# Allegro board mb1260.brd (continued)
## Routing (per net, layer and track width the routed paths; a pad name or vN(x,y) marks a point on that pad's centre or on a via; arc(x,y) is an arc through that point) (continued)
STMOD+_UART4_TXD: length 79.6
  TOP w0.127: U8.E12 v2(38.74,48.76)
  BOTTOM w0.127: P1.17 74.91,74.5 76.26,73.15 76.26,56.45 65.66,45.85 65.66,36.58 65.28,36.2 63.12,36.2 62.74,36.58 62.74,39.75 61.85,40.64 60.96,40.64 59.31,42.29 57.91,42.29 57.84,42.37 57.8,42.37 50.39,49.78 42.26,49.78 41.63,49.15 41.29,49.15 41.17,49.26 40.5,49.26 40,48.76 v2(38.74,48.76)
SYS_B_USER: length 76.7
  TOP w0.127: U8.N3 v2(32.24,42.91)
  L4_SIG w0.102: v1(35.81,23.11) 35.31,23.62 35.31,24.64 35.81,25.15 35.81,34.39 34.44,35.76 34.44,40.26 33.32,41.38 33.32,43.12 33.19,43.26 32.6,43.26 v2(32.24,42.91)
  BOTTOM w0.127: v1(35.81,23.11) 36.45,23.11 37.33,22.24 55.96,22.24 56.22,21.97 60.8,21.97 63.47,24.64 64.52,24.64 69.9,30.02 69.9,38.02 71.88,40.01 71.88,42.75 72.14,43 SB33.1
SYS_LD_USER1: length 50.5
  TOP w0.127: v1(10.67,50.67) 11.05,50.29 13.66,50.29 21.62,42.33 21.62,34.2 23.18,32.64 34.29,32.64 34.75,33.1 34.75,35.85 33.95,36.65 33.95,38.14 32.56,39.52 U8.R3
  BOTTOM w0.127: v1(10.67,50.67) 9.65,51.69 R47.1
SYS_LD_USER2: length 50.9
  TOP w0.127: U8.R4 32.97,41.69 32.97,39.73 34.33,38.37 34.33,36.81 35.13,36.01 35.13,32.84 34.54,32.26 22.99,32.26 21.21,34.04 21.21,42.16 13.46,49.91 10.79,49.91 v1(10.67,49.78)
  BOTTOM w0.127: R48.1 10.29,49.4 v1(10.67,49.78)
SYS_STLINK_JTCK: length 17.3
  TOP w0.127: v1(48.45,58.15) 48.51,58.09 48.51,57.38 48.53,57.36 48.53,57 SB12.2 49.69,56.87 R38.2 ; U8.A14 39.71,51.27 40.22,51.78 v2(40.22,51.98)
  BOTTOM w0.127: v1(48.45,58.15) 48.51,58.09 48.51,54.36 47.88,53.72 43.31,53.72 41.8,52.21 40.87,52.21 40.64,51.98 v2(40.22,51.98)
SYS_STLINK_JTDO-SWO: length 17.1
  TOP w0.127: U8.A10 37.11,51.97 37.31,52.17 37.31,52.79 37.57,53.05 37.57,53.27 v2(37.6,53.3) ; v1(46.86,55.91) 48.49,55.91 48.62,55.78 48.62,54.88 SB13.2 48.69,54.86 R40.2
  BOTTOM w0.127: v1(46.86,55.91) 45.97,55.91 44.65,54.58 38.94,54.58 37.66,53.3 v2(37.6,53.3)
SYS_STLINK_JTMS: length 16.9
  TOP w0.127: v2(41.27,51.82) 41.15,51.82 U8.A15 ; v1(49.07,58.29) 48.66,58.7 SB11.2 48.69,59.44 R32.2
  BOTTOM w0.127: v2(41.27,51.82) 42.04,51.82 42.8,52.58 44.69,52.58 45.33,53.21 48.01,53.21 49.07,54.28 v1(49.07,58.29)
T_JTCK: length 29.7
  TOP w0.127: U2.26 44.56,74.59 43.84,73.87 U2.15 43.84,71.85 44.96,70.74 48.9,70.74 49.66,69.98 49.66,65.82 46.74,62.9 46.74,58.6 47.68,57.66 SB12.1
T_JTMS: length 19.2
  TOP w0.127: v1(52.07,73.15) 52.07,74.42 R23.1 51.41,75.08 U2.27 ; SB11.1 47.68,59.61 48.01,59.94 v1(48.01,60.83)
  L4_SIG w0.102: v1(48.01,60.83) 48.01,64.77 50.8,67.56 50.8,70.87 52.07,72.14 v1(52.07,73.15)
T_NRST: length 15.2
  TOP w0.127: SB10.1 47.81,62.48 47.81,62.49 47.88,62.56 47.88,63.5 50.04,65.66 50.04,70.48 49.28,71.25 45.6,71.25 45.34,71.5 U2.18
T_SWDIO_IN: length 1.5
  TOP w0.127: 51.44,74.04 51.39,74.08 U2.25
T_SWO: length 29.4
  TOP w0.127: SB13.1 46.86,54.86 45.47,56.25 45.47,62.36 48.9,65.79 v1(48.9,66.8) ; v1(46.61,76.45) 47.24,77.08 U2.31
  BOTTOM w0.127: v1(48.9,66.8) 49.4,67.31 49.4,73.66 v1(46.61,76.45)
TAG_NRST: length 8.2
  TOP w0.127: R28.1 53.47,62.36 54.1,62.99 56.52,62.99 57.15,62.36 57.15,60.83 CN9.10
TAG_SWCLK: length 3.7
  TOP w0.127: 55.37,56.52 52.58,56.52 52.45,56.39 R38.1
TAG_SWDIO: length 3.8
  TOP w0.127: CN9.2 52.07,59.05 R32.1
TAG_SWO: length 12
  TOP w0.127: R40.1 51.69,53.21 52.32,52.58 57.66,52.58 58.17,53.09 58.17,54.74 57.66,55.24 CN9.6
USB_OTGFS_CN_N: length 3.3
  BOTTOM w0.155: CN18.2 51.95,4.99 52.08,5.12 52.08,5.8 51.25,6.64 U22.6
USB_OTGFS_CN_P: length 3.3
  BOTTOM w0.155: U22.4 53.15,6.61 52.47,5.93 52.47,5.12 52.6,4.99 CN18.3
USB_OTGFS_ID: length 57.3
  TOP w0.127: v2(42.64,48.87) 42.36,49.15 41.4,49.15 41.15,49.4 40.68,49.4 U8.D15
  L4_SIG w0.102: v2(42.64,48.87) 42.77,48.74 46.96,48.74 48.77,46.94 48.77,46.15 54.74,40.18 54.74,38.48 55.88,37.34 55.88,27.64 56.26,27.26 56.26,23.65 56.92,22.99 56.92,12.37 v1(55.6,11.05)
  BOTTOM w0.127: CN18.4 53.25,5.47 54.71,6.93 U23.1 54.71,9.37 55.6,10.26 v1(55.6,11.05)
USB_OTGFS_N: length 55.4
  TOP w0.155: v1(51.83,11.27) 52,11.44 52,12.79 55.02,15.8 55.02,46.98 51.84,50.16 41.18,50.16 40.88,49.87 40.5,49.87 U8.C15
  BOTTOM w0.155: U22.1 51.25,9.92 52,10.67 52,11.11 v1(51.83,11.27)
USB_OTGFS_OVCR: length 64.1
  TOP w0.127: U8.R12 38.31,41.83 38.31,41.05 38.43,40.92 38.43,40.32 v2(39.59,39.16) ; U14.3 61.54,9.47 R79.1 v1(61.59,8.13) 61.59,7.75 60.96,7.11 v1(60.96,5.08)
  L4_SIG w0.102: v2(39.59,39.16) 39.64,39.16 39.98,38.82 39.98,18.58 40.44,18.12 40.44,14.91 v1(38.99,13.46)
  BOTTOM w0.127: LD10.2 v1(60.96,5.08) ; v1(38.99,13.46) 38.99,12.95 39.88,12.07 40.77,12.07 42.04,10.8 46.05,10.8 46.3,11.05 50.67,11.05 51.69,12.07 58.22,12.07 61.59,8.69 v1(61.59,8.13)
USB_OTGFS_P: length 56
  TOP w0.155: U8.B15 40.5,50.25 40.72,50.25 41.02,50.55 51.99,50.55 55.4,47.14 55.4,15.65 52.38,12.63 52.38,11.44 v1(52.54,11.27)
  BOTTOM w0.155: U22.3 53.15,9.92 52.38,10.69 52.38,11.11 v1(52.54,11.27)
USB_OTGFS_PPWR_EN: length 46
  TOP w0.127: v2(41.53,46.48) 41.4,46.48 41.12,46.76 40.67,46.76 40.62,46.81 40.04,46.81 U8.H14 ; R72.1 59.94,17.91 57.71,20.14 57.71,22.68 56.52,23.88 v1(56.52,32.51)
  BOTTOM w0.127: v1(56.52,32.51) 55.5,33.53 55.5,40.31 52.32,43.48 45.92,43.48 45.78,43.62 45.28,43.62 44.83,44.07 44.83,44.96 44.07,45.72 42.27,45.72 41.66,46.33 41.66,46.35 v2(41.53,46.48)
USB_OTGFS_VBUS: length 73.5
  TOP w0.254: v2(41.91,48.39) 41.87,48.43 U8.E15
  TOP w0.508: U14.1 58.11,7.94 C77.1 56.62,9.3 55.22,9.3 54.47,10.05 v4(54.47,11.2) ; v4(50.01,10.41) 50.01,11.07 49.15,11.94 48.13,11.94 47.24,12.83 R77.2
  L4_SIG w0.508: v2(41.91,48.39) 41.91,47.75 42.29,47.37 46.41,47.37 47.19,46.58 47.19,45.73 48.14,44.78 49.23,44.78 54.18,39.83 54.18,38.28 55.37,37.08 55.37,27.43 55.75,27.05 55.75,12.27 54.69,11.2 v4(54.47,11.2) 53.85,11.2 52.78,12.27 51.31,12.27 50.01,10.97 v4(50.01,10.41)
  BOTTOM w0.254: CN18.1 51.3,5.34 50.61,6.03 50.22,6.03 U24.1
  BOTTOM w0.508: U24.1 49.67,7.13 R99.1 50.01,8.85 v4(50.01,10.41)
USB_OTGHS_CN_N: length 2.8
  TOP w0.155: U15.2 28.05,6.18 28.11,6.12 28.11,5.87 v1(27.92,5.68)
  BOTTOM w0.155: v1(27.92,5.68) 28.08,5.52 28.08,5.12 27.95,4.99 CN19.2
USB_OTGHS_CN_P: length 2.8
  TOP w0.155: U15.3 28.55,6.18 28.49,6.12 28.49,5.83 v1(28.63,5.68)
  BOTTOM w0.155: v1(28.63,5.68) 28.47,5.52 28.47,5.12 28.6,4.99 CN19.3
USB_OTGHS_ID: length 44.7
  TOP w0.127: U8.P12 38.08,42.25 38.08,41.27 38.05,41.24 38.05,40.14 39.29,38.9 39.29,38.77 v2(39.47,38.58) ; v1(29.59,5.72) 29.05,6.26 U15.4 29.16,6.86 29.72,6.86 32.13,9.27 32.13,10.8 39.24,17.91 v1(39.75,17.91)
  L4_SIG w0.102: v2(39.47,38.58) 39.62,38.43 39.62,18.03 v1(39.75,17.91)
  BOTTOM w0.127: CN19.4 29.25,5.37 v1(29.59,5.72)
USB_OTGHS_N: length 39.6
  TOP w0.155: U15.7 28.05,8.3 28.11,8.36 28.11,9.21 37.74,18.85 37.74,31.68 40.39,34.32 40.39,40.69 39.85,41.22 39.85,41.8 U8.R14
USB_OTGHS_OVCR: length 54.5
  TOP w0.127: v1(39.62,13.21) R78.2 ; U8.L13 v2(39.39,44.21)
  L4_SIG w0.102: v1(39.62,13.21) 40.56,12.27 45.67,12.27 48.64,15.24 49.78,15.24 51.18,16.64 51.94,16.64 53.52,18.21 53.52,18.63 53.52,32.46 52.96,33.02 52.96,37.16 48.34,41.78 45.97,41.78 45.72,42.04 42.82,42.04 42.1,42.75 41.29,42.75 41.14,42.61 40.85,42.61 40.7,42.75 40.59,42.75 40.04,43.31 39.88,43.31 39.75,43.43 39.75,43.84 v2(39.39,44.21)
USB_OTGHS_P: length 39.6
  TOP w0.155: U15.6 28.55,8.3 28.49,8.36 28.49,9.06 38.13,18.69 38.13,31.52 40.77,34.16 40.77,40.84 40.23,41.38 40.23,41.8 U8.R15
USB_OTGHS_PPWR_EN: length 60.7
  TOP w0.127: U8.K12 v2(38.74,44.86) ; v1(38.73,12.45) 38.73,12.9 38.3,13.34 37.97,13.34 37.97,11.93 U13.4
  L4_SIG w0.102: v2(38.74,44.86) 39.55,44.86 40.01,44.4 41.33,44.4 42.05,43.68 45.86,43.68 46.99,42.55 48.59,42.55 53.72,37.41 53.72,33.4 54.36,32.77 54.36,26.97 54.91,26.42 54.91,17.65 54.58,17.32 53.52,17.32 52.22,16.03 51.46,16.03 49.91,14.48 48.9,14.48 46.02,11.61 39.57,11.61 v1(38.73,12.45)
USB_OTGHS_VBUS: length 39.1
  TOP w0.127: 38.99,40.64 38.75,40.88 38.75,42.26 U8.P13
  TOP w0.381: 38.99,40.64 39.38,40.25 v2(39.38,39.98)
  L4_SIG w0.508: v2(39.38,39.98) 38.89,39.49 38.89,38.89 37.91,37.91 37.91,34.94 37.47,34.49 37.47,28.3 38.53,27.23 38.53,21.62 33.1,16.18 v1(31.7,16.18)
  BOTTOM w0.508: R98.1 31.37,9.91 31.7,10.24 v1(31.7,16.18)
USB_RENUMN: length 2.3
  TOP w0.127: U2.38 47.84,81.88 48.13,82.17 48.26,82.17 R7.2
USB_STLK_CN_N: length 3.4
  TOP w0.155: U21.1 53.78,90.62 52.98,91.42 52.98,91.89 53.11,92.02 CN1.2
USB_STLK_CN_P: length 3.4
  TOP w0.155: U21.3 51.88,90.62 52.59,91.33 52.59,91.89 52.46,92.02 CN1.3
USB_STLK_ID: length 3.1
  TOP w0.127: CN1.4 51.81,91.96 R9.2
USB_STLK_N: length 13.9
  TOP w0.155: U21.6 53.78,85.66 53.09,84.96 53.09,84.51 53.98,83.62 53.98,78.74 52.88,77.64 50.77,77.64 50.72,77.59 U2.32
USB_STLK_P: length 13.3
  TOP w0.155: U2.33 50.69,78.08 50.75,78.03 52.72,78.03 53.59,78.9 53.59,83.46 52.7,84.35 52.7,84.9 R10.2 U21.4
VCAP1: length 12.2
  TOP w0.254: U8.M10 v2(37.44,43.56)
  TOP w0.508: v1(44.4,37.72) 44.4,38.04 43.74,38.7 C58.2
  L4_SIG w0.381: v2(37.44,43.56) 37.72,43.56 38.25,43.03 38.25,42.7 38.89,42.05 38.89,42.05 39.2,41.74 40.6,41.74 41.19,41.16 41.62,41.16 42.3,40.48 42.3,40.45
  L4_SIG w0.457: v1(44.4,37.72) 44.4,38.35 42.3,40.45
VCAP2: length 5.3
  TOP w0.254: v2(39.39,47.46) 39.07,47.78 U8.F13
  TOP w0.508: v1(42.67,48.26) 43.36,48.26 C49.2
  BOTTOM w0.508: v2(39.39,47.46) 39.71,47.46 40.01,47.75 42.16,47.75 v1(42.67,48.26)
VCP_RX: length 35.4
  TOP w0.127: SB8.1 41.97,68.33 47.12,68.33 CN6.2 ; v2(40.82,47.13) U8.G15
  L4_SIG w0.102: v2(40.82,47.13) 40.82,48 42.48,49.66 45.47,49.66 46.35,50.55 46.35,57.91 47.57,59.13 47.57,66.62 48.26,67.31 CN6.2
VCP_TX: length 32.5
  TOP w0.127: CN6.1 45.26,69.01 SB9.1 ; U8.H15 40.81,46.48 v2(40.9,46.39)
  L4_SIG w0.102: CN6.1 46.48,68.71 46.48,67.06 47.24,66.29 47.24,59.44 46.05,58.24 46.05,50.8 45.34,50.09 41.25,50.09 41.08,49.92 41.08,49.51 40.47,48.9 40.47,46.83 v2(40.9,46.39)
VL: length 12.3
  TOP w0.508: 25.64,24.51 C72.2 26.29,23.9 ; 23.65,25.27 L4.2 ; L4.2 24.26,24.62 ; L4.2 24.87,25.27 ; L6.1 26.8,21.18 ; L6.1 25.32,20.4 ; L6.1 28.27,20.4 ; 24.27,20.4 U12.1 23.86,21 ; C73.2 25.48,22.61 ; C73.2 24.69,23.57 ; C73.2 23.9,22.61 ; C73.2 24.69,21.64 ; 25.96,25.78 C70.2 26.44,26.26
VREF+: length 134.1
  TOP w0.254: U8.P1 31.15,42.58 31.05,42.48 30.92,42.48 29.51,41.07 29.51,39.85 28.27,38.61 C59.2
  TOP w0.508: C59.2 28.19,37.34 C64.1 28.31,36.21 R62.1 27.9,34.01 v1(23.6,34.01) ; C50.2 R53.2 62.48,45.85 62.74,46.1 64.64,46.1 65.53,45.21 v1(65.53,6.99)
  L4_SIG w0.508: v1(26.24,7.59) 26.24,8.59 27.08,9.42 45.06,9.42 46.95,7.53 46.96,7.54 47.53,7.54 47.58,7.49 61.85,7.49 62.87,6.48 65.02,6.48 v1(65.53,6.99)
  BOTTOM w0.508: v1(26.24,7.59) 23.39,7.59 19.24,11.75 19.24,29.65 v1(23.6,34.01)
WIFI_CH_PD: length 67
  TOP w0.127: U8.D11 37.75,49.08 37.44,48.77 v2(37.44,48.74)
  BOTTOM w0.127: CN14.6 7.34,24.66 7.34,26.09 R95.2 12.49,31.24 12.49,47.17 14.78,49.45 14.78,53.55 16.61,55.37 17.18,55.37 17.81,55.37 20.73,58.29 30.4,58.29 31.3,57.39 31.67,57.39 31.96,57.1 33.36,57.1 34.05,56.41 34.05,55.55 34.54,55.05 34.54,52.45 34.97,52.02 35.56,52.02 35.76,51.82 35.76,51.33 36.35,50.75 37.62,50.75 37.82,50.55 37.82,49.15 37.44,48.76 v2(37.44,48.74)
WIFI_GPIO_0: length 71.1
  TOP w0.127: U8.A8 35.76,51.08 35.76,51.99 36.22,52.45 36.22,52.78 36.65,53.21 v2(36.65,53.47)
  BOTTOM w0.127: CN14.3 7.37,21.79 5.38,21.79 4.65,22.53 4.65,25.93 R93.2 11.66,32.94 11.66,47.6 13.39,49.33 13.39,53.23 16.29,56.13 17.49,56.13 20.41,59.05 30.71,59.05 31.07,58.7 33.03,58.7 34.32,57.4 35.15,57.4 36.65,55.91 v2(36.65,53.47)
WIFI_GPIO_2: length 72.5
  TOP w0.127: v1(37.97,55.63) 38.4,55.19 38.4,52.81 38.18,52.58 38.18,51.41 38.1,51.33 38.1,50.71 U8.B11
  BOTTOM w0.127: v1(37.97,55.63) 37.54,56.06 37.16,56.06 35.38,57.84 34.43,57.84 33.18,59.08 31.22,59.08 30.87,59.44 20.25,59.44 17.33,56.52 16.13,56.52 13,53.39 13,49.64 11.25,47.89 11.25,33.93 R96.2 3.33,26.01 3.33,24.64 4.27,23.7 4.27,22.35 CN14.5
WIFI_RST: length 59.6
  TOP w0.127: U8.A7 35.04,51.15 v2(35.04,51.56)
  BOTTOM w0.127: v2(35.04,51.56) 34.62,51.56 34.14,52.04 34.14,53.77 32.93,54.98 32.93,56.17 32.42,56.68 31.84,56.68 31.51,57.01 31.14,57.01 30.24,57.91 20.89,57.91 17.92,54.94 16.76,54.94 15.16,53.34 15.16,49.07 12.88,46.78 12.88,30.35 R94.2 8.56,26.04 8.56,23.34 CN14.4
WIFI_RX: length 63.9
  TOP w0.102: 38.74,52.07 38.41,51.74 U8.A12
  TOP w0.127: 38.74,52.07 38.74,52.58 v2(38.86,52.7)
  BOTTOM w0.127: v2(38.86,52.7) 37.08,52.7 36.86,52.48 36.17,52.48 35.99,52.3 35.23,52.3 34.95,52.58 34.95,53.64 35.13,53.82 35.13,56.44 34.54,57.02 33.98,57.02 33.44,57.56 32.03,57.56 31.83,57.77 31.45,57.77 30.55,58.67 20.57,58.67 17.65,55.75 16.45,55.75 13.77,53.07 13.77,49.07 12.11,47.42 12.11,32.38 6.68,26.95 R92.1
WIFI_TX: length 60.5
  TOP w0.102: v2(36.8,48.13) 37.06,48.39 37.72,48.39 U8.D12
  BOTTOM w0.102: v2(36.8,48.13) 36.8,48.14 36.2,48.74 35.36,48.74 34.24,49.87 34.24,50.5 33.29,51.44 33.29,51.82
  BOTTOM w0.127: R97.2 13.26,29.46 13.26,46.53 15.54,48.82 15.54,53.14 16.97,54.56 18.07,54.56 18.44,54.93 19.36,54.93 20.1,55.67 20.1,56.32 21.31,57.53 30.08,57.53 30.98,56.63 31.35,56.63 31.68,56.3 32.26,56.3 32.55,56.01 32.55,54.6 33.29,53.85 33.29,51.82

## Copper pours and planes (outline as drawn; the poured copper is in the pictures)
1V8 on TOP: 1.84,44.51 1.52,44.83 1.52,48.13 1.78,48.39 4.45,48.39 4.57,48.51 4.57,50.04 4.83,50.29 9.02,50.29 9.4,49.91 9.4,45.59 7.75,43.94 7.75,43.31 6.73,43.31 6.73,43.94 6.16,44.51
1V8 on L4_SIG: 17.65,64.39 17.91,64.14 17.91,61.34 17.53,60.96 10.92,60.96 9.78,59.82 9.78,49.66 5.59,45.47 5.59,41.66 5.21,41.27 1.91,41.27 1.52,41.66 1.52,46.41 6.48,51.36 6.48,62.48 8.38,64.39
3V3 on TOP (solid shape): 5.72,65.02 6.05,65.35 6.32,65.08 5.78,64.54 5.71,64.61 5.64,64.54 5.1,65.08 5.38,65.36
3V3 on BOTTOM (solid shape): 25.34,74.33 25.4,74.39 25.67,74.12 25.13,73.58 25.09,73.62 25.05,73.58 24.51,74.12 24.78,74.39 24.84,74.33 25.09,74.58
3V3 on TOP: 9.14,43.43 11.43,43.43 11.68,43.18 11.68,40.01 11.3,39.62 9.02,39.62 8.64,40.01 8.64,42.93
3V3 on TOP: 58.67,65.66 62.23,65.66 62.61,66.04 62.61,67.31 62.48,67.44 61.85,67.44 61.59,67.69 58.8,67.69 58.55,67.44 54.1,67.44 53.72,67.06 53.72,65.02 54.1,64.64 57.66,64.64
3V3 on L3_VCC: outline of 97 points within 0.51,0.51 80.49,96.49
3V3_ST_LINK on TOP: 57.02,73.66 62.23,73.66 62.48,73.41 62.48,72.01 62.23,71.75 60.83,71.75 60.38,72.21 56.95,72.21 56.77,72.39 56.77,73.41
3V3_ST_LINK on L3_VCC: 38.97,72.14 37.82,73.28 33.25,73.28 32.77,73.77 32.77,96.49 78.49,96.49 79.91,95.9 80.49,94.49 80.49,74.17 70.51,74.17 68.47,72.14
5V on TOP: 64.14,67.18 64.39,67.44 64.39,69.22 64.14,69.47 64.14,70.74 64.26,70.87 65.15,70.87 65.79,70.23 66.17,70.23 66.29,70.1 66.29,69.09 66.42,68.96 66.42,67.69 66.04,67.31 66.04,66.17 65.91,66.04 64.39,66.04 64.14,66.29
5V on TOP: 80.44,45.91 80.44,33.33 79.76,32.64 79.65,32.64 79.29,32.28 75.93,32.28 75.83,32.38 75.83,32.86 76.09,33.12 76.09,34.46 76.08,34.46 75.83,34.71 75.83,35.25 76.1,35.52 76.1,36.94 76.09,36.94 75.83,37.2 75.83,37.86 76.1,38.13 76.1,39.49 76.07,39.49 75.83,39.72 75.83,40.39 76.15,40.71 76.15,42.01 76.15,42.01 75.83,42.33 75.83,42.95 76.18,43.29 76.18,44.05 76.17,44.06 76.17,44.24 74.95,45.46 74.95,66.51 74.01,67.44 71.12,67.44 70.66,67.9 70.66,73.21 71.11,73.66 74.71,73.66 75.14,73.22 77.38,73.22 80.26,70.34
5V on L3_VCC: 55.86,12.57 55.37,13.06 55.37,18.52 53.95,19.94 40.66,19.94 39.37,18.65 39.37,13.69 38.63,12.95 32.74,12.95 27.41,18.29 18.65,18.29 12.7,24.24 12.7,30.76 13.44,31.5 17.17,31.5 25.68,22.99 49.51,22.99 51.79,25.27 66.55,25.27 66.8,25.02 66.8,21.46 67.69,20.57 73.41,20.57 74.55,21.72 74.55,50.4 73,51.94 63.73,51.94 63.37,52.3 63.37,71.63 68.69,71.63 70.72,73.66 80.49,73.66 80.49,11.02 80.39,10.92 65.91,10.92 62.36,14.48 60.73,14.48 58.82,12.57
5V on L4_SIG: 65.43,70.48 68.2,70.48 71.37,73.66 74.42,73.66 75.18,72.9 75.18,69.98 74.68,69.47 71.12,69.47 70.48,68.83 70.48,66.55 69.09,65.15 66.55,65.15 65,66.7 65,70.05
5V_ST_LINK on TOP (solid shape): 65.78,80.02 65.84,80.08 66.11,79.81 65.58,79.28 65.53,79.32 65.49,79.28 64.95,79.81 65.22,80.08 65.28,80.02 65.53,80.27
5V_ST_LINK on TOP: 65.02,79.88 66.8,79.88 66.93,79.76 66.93,78.36 66.8,78.23 66.04,78.23 65.66,77.85 65.66,76.96 65.53,76.83 64.64,76.83 64.52,76.96 64.52,79.38
5V_USB_FS on TOP: 68.68,37.03 74.45,37.03 74.63,36.86 74.63,35.51 74.6,35.48 70.33,35.48 69.65,34.8 68.63,34.8 68.5,34.92 68.5,36.86
5V_USB_FS on BOTTOM: 48.88,8.01 48.74,7.87 46.99,7.87 46.86,8 46.86,10.41 47.17,10.72 48.92,10.72 49.12,10.52 49.12,10.03 48.88,9.79
5V_USB_FS on L4_SIG: 49.07,10.87 49.3,10.64 49.3,9.04 49.02,8.76 47.5,8.76 47.12,9.14 47.12,10.67 47.32,10.87
5V_USB_FS on L4_SIG: 68.38,35.53 69.82,35.53 70,35.36 70,33.87 69.88,33.75 68.34,33.75 68.22,33.87 68.22,35.38
5V_USB_HS on TOP: 68.66,41.15 68.66,42.21 68.94,42.49 70.59,42.49 70.92,42.16 74.57,42.16 74.65,42.09 74.65,40.77 74.6,40.72 70.82,40.72 70.61,40.92 68.88,40.92
5V_USB_HS on BOTTOM: 26.63,7.35 26.11,6.83 26.11,6.12 26.24,5.99 27.33,5.99 27.53,6.2 28.32,6.2 28.42,6.3 28.42,7.24 28.31,7.35
5V_USB_HS on L4_SIG: 69.29,42.49 71.86,42.49 72.52,41.83 72.52,41.33 72.26,41.07 69.22,41.07 68.94,41.35 68.94,42.14
5V_USB_HS on L4_SIG: 26.66,5.85 26.54,5.97 26.24,5.97 26.09,6.12 26.09,7.04 26.21,7.16 26.52,7.16 26.92,7.57 28.37,7.57 28.5,7.44 28.5,6.22 28.4,6.12 27.74,6.12 27.47,5.85
5V_USB_ST_LINK on TOP (solid shape): 66.15,80.47 65.86,80.18 65.53,80.52 65.19,80.19 64.92,80.46 65.46,81 65.53,80.93 65.61,81.01
5V_USB_ST_LINK on TOP: 68.63,34.29 70.36,34.29 70.37,34.28 70.38,34.29 70.79,34.29 70.87,34.37 74.55,34.37 74.57,34.34 74.57,32.54 73.99,31.95 70.69,31.95 70.1,31.37 68.58,31.37 68.35,31.6 68.35,34.01
5V_USB_ST_LINK on TOP: 60.71,81.92 60.71,78.61 60.58,78.49 55.75,78.49 55.63,78.61 55.63,80.39 55.88,80.64 57.53,80.64 57.78,80.9 57.78,83.19 58.04,83.44 62.23,83.44 63.25,82.42 66.29,82.42 66.67,82.04 66.67,80.77 66.42,80.52 64.9,80.52 64.52,80.9 62.99,80.9 61.72,82.17 60.96,82.17
5V_USB_ST_LINK on BOTTOM: 64.72,82.35 66.5,82.35 66.67,82.17 66.67,80.8 66.42,80.54 64.85,80.54 64.47,80.92 64.47,82.09
5V_USB_ST_LINK on BOTTOM: 68.96,31.37 67.56,31.37 67.31,31.62 67.31,33.78 67.44,33.91 68.96,33.91 69.09,33.78 69.09,31.5
GND on TOP (solid shape): 37.98,73.78 38.31,74.11 38.58,73.85 38.04,73.31 37.97,73.38 37.9,73.3 37.36,73.84 37.64,74.12
GND on TOP (solid shape): 49.38,14.55 49.31,14.48 49.38,14.4 48.84,13.86 48.56,14.15 48.9,14.48 48.57,14.82 48.84,15.09
GND on BOTTOM (solid shape): 23.49,74.33 23.55,74.39 23.82,74.12 23.28,73.58 23.24,73.62 23.19,73.58 22.66,74.12 22.92,74.39 22.99,74.33 23.24,74.58
GND on TOP: 2.51,0.51 1.1,1.1 0.51,2.51 0.51,94.49 1.1,95.9 2.51,96.49 78.49,96.49 79.91,95.9 80.49,94.49 80.49,73.97 75.55,73.97 74.46,75.06 70.82,75.06 70.64,75.23 69.68,75.23 69.13,74.68 69.13,72.87 68.86,72.6 66.82,72.6 66.67,72.45 66.8,72.45 68.53,70.72 68.53,43.46 67.34,42.27 67.34,31.65 68.28,30.71 80.26,30.71 80.49,30.48 80.49,2.51 79.91,1.1 78.49,0.51 55.91,0.51 55.91,2 55.51,2.39 54.44,2.39 54.04,2 54.04,0.51 51.16,0.51 51.16,2 50.76,2.39 49.69,2.39 49.29,2 49.29,0.51 31.91,0.51 31.91,2 31.51,2.39 30.44,2.39 30.04,2 30.04,0.51 27.16,0.51 27.16,2 26.76,2.39 25.69,2.39 25.29,2 25.29,0.51 ; 18 cut-outs
GND on TOP: 25.91,46.35 21.34,46.35 20.95,46.74 20.95,50.8 21.34,51.18 23.75,51.18 24.18,50.75 25.12,50.75 25.45,50.42 25.45,49.86 25.91,49.4 28.5,49.4 28.7,49.2 29.59,49.2 29.72,49.07 29.72,48.9 29.59,48.77 28.68,48.77 28.37,49.07 25.27,49.07 25.17,49.17 24.31,49.17 24.18,49.05 24.18,47.5 24.38,47.29 26.37,47.29 26.54,47.12 28.32,47.12 28.96,47.75 30.1,47.75 30.1,47.5 29.84,47.24 29.08,47.24 28.45,46.61 26.16,46.61
GND on TOP: 57.02,71.75 60.33,71.75 60.58,71.5 60.58,70.61 60.33,70.36 59.31,70.36 59.18,70.23 57.02,70.23 56.77,70.48 56.77,71.5
GND on TOP: 59.56,69.85 61.34,69.85 61.59,69.6 61.59,68.2 61.34,67.94 59.31,67.94 59.18,68.07 59.18,69.47
GND on L2_GND: 2.51,0.51 1.1,1.1 0.51,2.51 0.51,94.49 1.1,95.9 2.51,96.49 78.49,96.49 79.91,95.9 80.49,94.49 80.49,2.51 79.91,1.1 78.49,0.51 55.91,0.51 55.91,2 55.51,2.39 54.44,2.39 54.04,2 54.04,0.51 51.16,0.51 51.16,2 50.76,2.39 49.69,2.39 49.29,2 49.29,0.51 31.91,0.51 31.91,2 31.51,2.39 30.44,2.39 30.04,2 30.04,0.51 27.16,0.51 27.16,2 26.76,2.39 25.69,2.39 25.29,2 25.29,0.51 ; 2 cut-outs
GND on L4_SIG: 68.05,18.75 73.1,18.75 74.35,19.99 74.35,23.5 75.84,24.99 75.84,44.81 74.47,46.18 74.47,48.74 72.85,50.37 68.91,50.37 68.38,49.83 68.38,43.46 68.83,43 72.26,43 73.38,41.88 73.38,29.26 67.56,23.44 67.56,19.23
GND on L4_SIG: 2.51,0.51 1.1,1.1 0.51,2.51 0.51,94.49 1.1,95.9 2.51,96.49 78.49,96.49 79.91,95.9 80.49,94.49 80.49,2.51 79.91,1.1 78.49,0.51 55.91,0.51 55.91,2 55.51,2.39 54.44,2.39 54.04,2 54.04,0.51 51.16,0.51 51.16,2 50.76,2.39 49.69,2.39 49.29,2 49.29,0.51 31.91,0.51 31.91,2 31.51,2.39 30.44,2.39 30.04,2 30.04,0.51 27.16,0.51 27.16,2 26.76,2.39 25.69,2.39 25.29,2 25.29,0.51 ; 1 cut-out
GND on L4_SIG: 27.97,80.11 37.85,80.11 38.66,79.3 38.66,72.8 36.35,70.48 33.53,70.48 28.42,65.38 27.38,65.38 26.52,66.24 26.52,78.66
GND on L4_SIG: 54.18,59.84 60.35,59.84 61.01,59.18 61.01,43.54 60.1,42.62 55.07,42.62 53.14,44.55 53.14,58.8
GND on L4_SIG: 21.39,51.16 23.77,51.16 24.26,50.67 25.04,50.67 25.43,50.29 25.43,49.89 26.19,49.12 29.39,49.12 29.57,48.95 29.57,47.78 28.4,46.61 26.14,46.61 25.93,46.41 21.31,46.41 21.03,46.69 21.03,50.8
GND on L4_SIG: 36.22,86.11 41.99,80.34 48.26,80.34 49.28,79.32 49.28,78.33 50.24,77.37 57.23,77.37 57.56,77.04 57.56,74.14 57.33,73.91 56.18,73.91 55.58,73.3 55.6,73.28 55.6,70.46 55.37,70.23 54.46,70.23 54.15,70.54 54.15,74.27 52.12,76.3 48.46,76.3 47.52,77.24 44.98,77.24 43.71,78.51 42.19,78.51 39.04,81.66 23.11,81.66 22.86,81.92 22.86,82.68 23.01,82.83 23.09,82.83 23.11,82.85 23.95,82.85 27.2,86.11
GND on L5_GND: 2.51,0.51 1.1,1.1 0.51,2.51 0.51,94.49 1.1,95.9 2.51,96.49 78.49,96.49 79.91,95.9 80.49,94.49 80.49,2.51 79.91,1.1 78.49,0.51 55.91,0.51 55.91,2 55.51,2.39 54.44,2.39 54.04,2 54.04,0.51 51.16,0.51 51.16,2 50.76,2.39 49.69,2.39 49.29,2 49.29,0.51 31.91,0.51 31.91,2 31.51,2.39 30.44,2.39 30.04,2 30.04,0.51 27.16,0.51 27.16,2 26.76,2.39 25.69,2.39 25.29,2 25.29,0.51
VDD on TOP (solid shape): 49.38,16.32 49.31,16.26 49.38,16.18 48.84,15.64 48.56,15.92 48.9,16.26 48.57,16.59 48.84,16.86
VDD on TOP: 56.01,70.48 56.83,69.66 58.74,69.66 58.8,69.6 58.8,68.2 58.67,68.07 52.45,68.07 52.2,68.33 52.2,70.23 52.45,70.48
VDD on L3_VCC: 32.36,32.89 32,33.25 32,36.94 31.47,37.47 28.05,37.47 27.69,37.82 27.69,42.78 27.18,43.29 27.18,54.63 27.41,54.86 37.32,54.86 38.99,56.54 38.99,71.63 57.4,71.63 57.4,68.18 56.92,67.69 54.12,67.69 50.29,63.86 50.29,52.05 44.32,46.08 44.32,38.33 43.58,37.59 39.77,37.59 39.37,37.19 39.37,33.38 38.88,32.89
VIN on TOP: 14.86,24.13 17.65,24.13 18.03,23.75 18.03,21.72 17.53,21.21 13.34,21.21 12.32,22.23 12.32,23.75 10.35,25.72 9.21,25.72 8.89,26.04 8.89,30.86 9.53,31.5 12.32,31.5 12.7,31.11 12.7,26.29
(no net) on BOTTOM: 55.91,0.51 55.91,2 55.51,2.39 54.44,2.39 54.04,2 54.04,0.51 51.16,0.51 51.16,2 50.76,2.39 49.69,2.39 49.29,2 49.29,0.51 31.91,0.51 31.91,2 31.51,2.39 30.44,2.39 30.04,2 30.04,0.51 27.16,0.51 27.16,2 26.76,2.39 25.69,2.39 25.29,2 25.29,0.51 14.3,0.51 14.3,14.09 0.54,14.09 0.51,14.13 0.51,94.49 1.1,95.9 2.51,96.49 78.49,96.49 79.91,95.9 80.49,94.49 80.49,2.51 79.91,1.1 78.49,0.51 ; 6 cut-outs
ARD_A1 on BOTTOM (solid shape): 69.29,65.84 69.23,65.78 69.48,65.53 69.23,65.28 69.29,65.22 69.02,64.95 68.48,65.49 68.52,65.53 68.48,65.58 69.02,66.11
ARD_A4 on BOTTOM (solid shape): 19.81,8.92 19.88,8.99 20.42,8.45 20.15,8.18 19.82,8.51 19.48,8.17 19.2,8.46 19.74,9
ARD_A5 on BOTTOM (solid shape): 19.94,5.23 20.01,5.3 20.55,4.76 20.28,4.49 19.95,4.83 19.61,4.49 19.33,4.77 19.87,5.31
ARD_D5 on BOTTOM (solid shape): 69.29,69.88 69.23,69.82 69.48,69.57 69.23,69.32 69.29,69.26 69.02,68.99 68.48,69.53 68.52,69.57 68.48,69.61 69.02,70.15
ARD_D13 on TOP (solid shape): 61.59,40.02 61.65,40.08 61.92,39.81 61.38,39.27 61.34,39.31 61.3,39.27 60.76,39.81 61.03,40.08 61.09,40.02 61.34,40.27
ARD_D14 on BOTTOM (solid shape): 18.03,8.92 18.1,8.99 18.64,8.45 18.37,8.18 18.04,8.51 17.7,8.17 17.42,8.46 17.96,9
ARD_D14 on BOTTOM (solid shape): 69.42,80.73 69.08,80.4 69.42,80.06 69.14,79.78 68.6,80.32 68.68,80.39 68.61,80.46 69.15,81
ARD_D15 on BOTTOM (solid shape): 18.17,5.23 18.23,5.3 18.77,4.76 18.5,4.49 18.17,4.83 17.83,4.49 17.55,4.77 18.09,5.31
ARD_D15 on BOTTOM (solid shape): 69.29,74.89 68.96,74.56 69.3,74.22 69.01,73.93 68.47,74.47 68.55,74.55 68.48,74.62 69.02,75.16
BLGND on L2_GND: 21.82,9.14 20.07,10.9 20.07,23.52 21.97,25.42 21.97,29.36 22.33,29.72 28.34,29.72 30.1,27.96 30.1,15.98 29.61,15.49 27.45,15.49 26.92,14.96 26.92,9.88 26.18,9.14
DMIC_VDD on TOP (solid shape): 6.3,65.73 6.03,65.46 5.97,65.52 5.71,65.27 5.46,65.52 5.4,65.46 5.13,65.73 5.67,66.27 5.71,66.22 5.76,66.27
DMIC_VDD on TOP (solid shape): 8.07,65.73 7.81,65.46 7.74,65.52 7.49,65.27 7.24,65.52 7.18,65.46 6.91,65.73 7.45,66.27 7.49,66.22 7.54,66.27
E5V on TOP: 68.81,40.41 70.21,40.41 70.46,40.16 70.46,40.13 71.07,39.52 74.52,39.52 74.63,39.42 74.63,38.2 74.57,38.15 70.36,38.15 70.21,38 68.81,38 68.68,38.13 68.68,40.28
E5V on TOP: 1.65,38.1 8.64,38.1 9.27,37.47 9.27,33.66 7.75,32.13 6.86,32.13 5.46,33.53 1.27,33.53 1.02,33.78 1.02,37.47
E5V on L4_SIG: 2.29,33.93 1.27,33.93 1.02,34.19 1.02,36.35 1.27,36.6 2.26,36.6 2.41,36.45 2.41,34.06
E5V on L4_SIG: 67.94,40.51 70.1,40.51 70.23,40.39 70.23,39.37 70.1,39.24 68.07,39.24 67.82,39.5 67.82,40.39
MIC_VDD1 on TOP (solid shape): 7.5,65.02 7.83,65.35 8.1,65.08 7.56,64.54 7.49,64.61 7.42,64.54 6.88,65.08 7.16,65.36
NETB2_1 on BOTTOM (solid shape): 74.04,35.06 74.1,35.13 74.37,34.86 73.83,34.32 73.79,34.36 73.74,34.32 73.21,34.86 73.47,35.13 73.54,35.06 73.79,35.32
NETC9_2 on TOP (solid shape): 66.37,71.56 66.31,71.5 66.56,71.25 66.31,71 66.37,70.93 66.1,70.67 65.56,71.2 65.6,71.25 65.56,71.29 66.1,71.83
NETC75_2 on TOP: 22.73,16.76 20.32,16.76 20.07,16.51 20.07,10.92 21.84,9.14 22.73,9.14 22.99,9.4 22.99,13.08 23.11,13.21 23.11,16.38
NETC86_2 on BOTTOM (solid shape): 74.04,42.3 74.1,42.36 74.37,42.1 73.83,41.56 73.79,41.6 73.74,41.56 73.21,42.1 73.47,42.36 73.54,42.3 73.79,42.55
NETCN15_5 on BOTTOM (solid shape): 18.29,8.01 18.35,8.07 18.62,7.81 18.08,7.27 18.03,7.31 17.99,7.27 17.45,7.81 17.72,8.07 17.78,8.01 18.03,8.26
NETCN15_5 on BOTTOM (solid shape): 20.06,8.01 20.12,8.07 20.39,7.81 19.86,7.27 19.81,7.31 19.77,7.27 19.23,7.81 19.5,8.07 19.56,8.01 19.81,8.26
NETCN15_6 on BOTTOM (solid shape): 18.42,4.33 18.48,4.39 18.75,4.12 18.21,3.58 18.17,3.62 18.12,3.58 17.58,4.12 17.85,4.39 17.91,4.33 18.17,4.58
NETCN15_6 on BOTTOM (solid shape): 20.2,4.33 20.26,4.39 20.53,4.12 19.99,3.58 19.94,3.62 19.9,3.58 19.36,4.12 19.63,4.39 19.69,4.33 19.94,4.58
NETCN16_8 on BOTTOM (solid shape): 23.24,75.23 23.31,75.3 23.84,74.76 23.57,74.49 23.24,74.83 22.91,74.49 22.62,74.77 23.16,75.31
NETCN16_8 on BOTTOM (solid shape): 25.09,75.23 25.16,75.3 25.7,74.76 25.43,74.49 25.1,74.83 24.76,74.49 24.48,74.77 25.02,75.31
NETCN17_24 on TOP (solid shape): 48.46,16.57 48.4,16.51 48.65,16.26 48.4,16 48.46,15.94 48.19,15.67 47.65,16.21 47.7,16.26 47.65,16.3 48.19,16.84
NETCN17_24 on TOP (solid shape): 48.46,14.79 48.4,14.73 48.65,14.48 48.4,14.23 48.46,14.17 48.19,13.9 47.65,14.43 47.7,14.48 47.65,14.52 48.19,15.06
NETD2_2 on TOP (solid shape): 67.28,71.32 67.21,71.25 67.29,71.17 66.75,70.63 66.47,70.92 66.81,71.25 66.47,71.58 66.74,71.85
NETR12_2 on TOP (solid shape): 61.96,40.46 61.67,40.18 61.33,40.52 61,40.19 60.73,40.45 61.27,40.99 61.34,40.92 61.42,41
NRST on TOP (solid shape): 49.12,62.4 49.08,62.36 49.12,62.31 48.58,61.78 48.31,62.04 48.37,62.11 48.12,62.36 48.37,62.61 48.31,62.67 48.58,62.94
NRST on BOTTOM (solid shape): 73.79,35.97 73.86,36.04 74.39,35.5 74.12,35.23 73.79,35.56 73.46,35.23 73.17,35.51 73.71,36.05
STLINK_RX on TOP (solid shape): 43.63,69.92 43.37,69.65 43.3,69.71 43.05,69.46 42.8,69.71 42.74,69.65 42.47,69.92 43.01,70.46 43.05,70.41 43.1,70.46
STLINK_TX on TOP (solid shape): 41.86,69.92 41.59,69.65 41.53,69.71 41.27,69.46 41.02,69.71 40.96,69.65 40.69,69.92 41.23,70.46 41.27,70.41 41.32,70.46
STM_RST on TOP (solid shape): 38.55,74.49 38.29,74.22 38.22,74.28 37.97,74.03 37.72,74.28 37.66,74.22 37.39,74.49 37.93,75.03 37.97,74.99 38.02,75.03
STMOD+_ADC_DAC on BOTTOM (solid shape): 70.21,65.61 70.13,65.53 70.2,65.46 69.66,64.92 69.4,65.19 69.73,65.53 69.39,65.86 69.67,66.15
STMOD+_I2C2_SCL on BOTTOM (solid shape): 70.2,74.59 70.16,74.55 70.2,74.51 69.66,73.97 69.4,74.24 69.46,74.3 69.21,74.55 69.46,74.8 69.4,74.86 69.66,75.13
STMOD+_I2C2_SDA on BOTTOM (solid shape): 70.33,80.43 70.29,80.39 70.33,80.35 69.79,79.81 69.52,80.08 69.58,80.14 69.33,80.39 69.58,80.64 69.52,80.7 69.79,80.97
STMOD+_TIM3_CH3 on BOTTOM (solid shape): 70.21,69.65 70.13,69.57 70.2,69.5 69.66,68.96 69.4,69.23 69.73,69.56 69.39,69.9 69.67,70.18
SYS_B_USER on BOTTOM (solid shape): 73.79,43.21 73.86,43.28 74.39,42.74 74.12,42.47 73.79,42.8 73.46,42.46 73.17,42.75 73.71,43.29
SYS_STLINK_JTCK on TOP (solid shape): 49.12,56.94 49.08,56.9 49.12,56.85 48.58,56.31 48.31,56.58 48.37,56.64 48.12,56.9 48.37,57.15 48.31,57.21 48.58,57.48
SYS_STLINK_JTDO-SWO on TOP (solid shape): 49.12,54.91 49.08,54.86 49.12,54.82 48.58,54.28 48.31,54.55 48.37,54.61 48.12,54.86 48.37,55.12 48.31,55.18 48.58,55.45
SYS_STLINK_JTMS on TOP (solid shape): 49.12,59.48 49.08,59.44 49.12,59.39 48.58,58.85 48.31,59.12 48.37,59.18 48.12,59.44 48.37,59.69 48.31,59.75 48.58,60.02
T_JTCK on TOP (solid shape): 48.21,57.23 47.88,56.89 48.21,56.56 47.94,56.29 47.4,56.83 47.47,56.9 47.39,56.97 47.93,57.51
T_JTMS on TOP (solid shape): 48.21,59.77 47.88,59.43 48.21,59.1 47.94,58.83 47.4,59.37 47.47,59.44 47.39,59.51 47.93,60.05
T_NRST on TOP (solid shape): 48.21,62.69 47.88,62.35 48.21,62.02 47.94,61.75 47.4,62.29 47.47,62.36 47.39,62.43 47.93,62.97
T_SWO on TOP (solid shape): 48.21,55.2 47.88,54.86 48.21,54.53 47.94,54.26 47.4,54.8 47.47,54.86 47.39,54.94 47.93,55.48
VCP_RX on TOP (solid shape): 41.28,69.21 41.61,69.54 41.88,69.27 41.34,68.73 41.27,68.8 41.2,68.73 40.66,69.27 40.94,69.55
VCP_TX on TOP (solid shape): 43.06,69.21 43.39,69.54 43.66,69.27 43.12,68.73 43.05,68.8 42.98,68.73 42.44,69.27 42.72,69.55
VL on TOP: 28.7,19.68 25.53,19.68 25.15,20.07 23.88,20.07 23.75,20.19 23.75,24.13 23.24,24.64 23.24,25.65 23.37,25.78 24.89,25.78 24.89,26.16 25.27,26.54 26.67,26.54 26.8,26.42 26.8,24 26.42,23.62 26.04,23.62 25.91,23.5 25.91,21.72 26.16,21.46 28.57,21.46 28.96,21.08 28.96,19.94

Small or netless copper shapes (teardrops, artwork), in the pictures only: 16 on BOTTOM

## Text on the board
BOTTOM: 6 | D
Ref Des/Silkscreen Bottom: B | D | SPKR | SPKL | GND | <- | PA6 | PA4 | PC4 | PF10 | PC0 | PC1 | 3V3 | 5V | NRST | <11.5V | VIN | USB HS | VCPTX | VCPRX | STLINK | VDD | USB FS | PH4 | PH5 | PA5 | PB4 | PB5 | PA1 | PH6 | PE4 | PE3 | PE6 | PB0 | PH3 | PE5 | PC5 | PA2 | PA3 | VREF+ | E5V | 3V3_STLINK | RESET | USER&WAKEUP | WIFI | RTS,PF8 | SCK,PI1 | PMOD#4 | RX,PF6 | MISO,PI2 | PMOD#3 | TX,PF7 | PMOD#2 | MOSI,PI3 | CTS,PF9 | NSS,PI0 | PMOD#1 | JTMS | 1 | 0 | SEL_1,PI10 | SEL_0,PH15 | UART | UART/SPI | SPI | JTCK | www.st.com/stm32f7-discovery | MB1260D | LCD | STM32F723E-DISCO
TOP: 1 | D
Ref Des/Silkscreen Top: S | D | 1V8 | 800mA | E5V | MAX | SPKR | SPKL | GND | NRST | Audio | 3V3 | 5V | VIN | A0 | A1 | A2 | A3 | A4 | A5 | <11.5V | Codec | B | A | USB HS | QSPI | STM32F723IEK | PSRAM | STLINK | USB FS | VDD | TMS | TCK | TRST | TDI | TDO | TAG | 3V3_STLINK | D15 | D14 | AVDD | D13 | D12 | D11 | D10 | D9 | D8 | D7 | D6 | D5 | D4 | D3 | D2 | D1 | D0 | 6 | 1 | PMOD | 10 | Table for P2 | Table for P1 | USB_HS | USB_FS | USB_STLINK | 12 | 7 | PI1 | PI2 | PI3 | PI0 | 11 | 20 | PH5 | PC2 | PC3 | PH4 | PF6 | PF7 | PH2 | PG12 | PF11 | PB11 | PC11 | PH14 | PH13 | PB0 | PA4 | PA15 | LineIN | LineOUT | VCP_TX | VCP_RX | JTMS | JTCK | MB1260D | www.st.com/stm32f7-discovery | STM32F723E-DISCO
User.6: 5 | D
User.7: 3 | D
User.8: D | 4
User.12: 2 | D
User.23: 1,6 | 6.1 | 8.9 | N/A | 90 OHM | 100 OHM | +/-10%
User.40: LCD
User.45: FIGURE | SIZE | 6.0 | 8.0 | 10.0 | 12.0 | 33.0 | 36.0 | 40.0 | 138.0 | 39.0 | 79.0 | 33.0x30.0 | 51.0x24.0 | 59.0x33.0 | TOLERANCE | +3.0/-3.0 | +2.0/-2.0 | +5.0/-5.0 | DRILL CHART: TOP to BOTTOM | ALL UNITS ARE IN MILS | PLATED | NON-PLATED | ROTATION | - | 90.000 | QTY | 35 | 196 | 231 | 393 | 2 | 32 | 54 | 3 | 4 | 1 | 964 | TOTAL HOLES:
